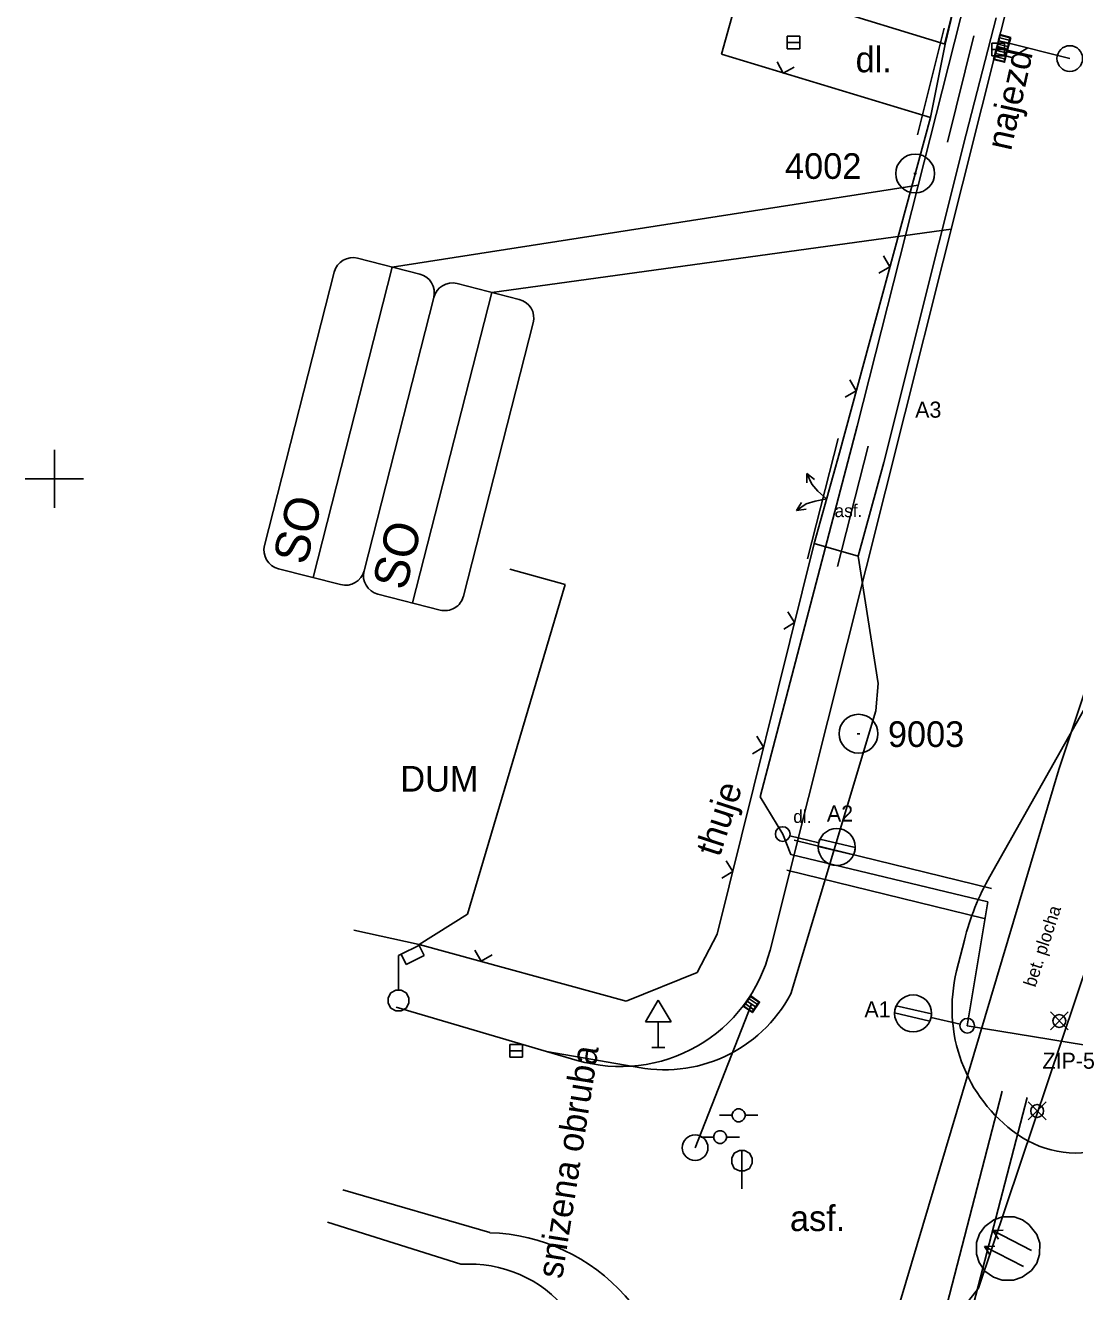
# Model space of a CAD drawing. Extents: x -733601 to -733291, y -1137892 to -1137187.
# Drawn here: x -733501.13 to -733460.25, y -1137631.66 to -1137582.33 of the extents above; entities that cross this region are included whole.
import ezdxf

# ---------------------------------------------------------------- set-up
doc = ezdxf.new("R2010")
doc.units = 0
for name, color, linetype in [('BP_NOVE_NAVRH', 7, 'Continuous'), ('BP_PBPP_pouzito_pro_map_podklady', 7, 'Continuous'), ('Default', 7, 'Continuous'), ('Krizky_Hektom_sit', 7, 'Continuous'), ('SIT_PROJ', 7, 'Continuous'), ('SIT_PUV_BUS', 7, 'Continuous')]:
    doc.layers.add(name, color=color, linetype=linetype)

# ---------------------------------------------------------------- blocks, each defined once
blk = doc.blocks.new('T_PS_1_1_2')
at = {"layer": 'Default'}
blk.add_line((-12.486, 3.717), (12.486, 3.717), dxfattribs=at)
for points in [[(10.986, 8), (-10.986, 8)], [(-12.486, 6.5), (-12.486, 1.5)], [(12.486, 1.5), (12.486, 6.5)], [(-10.986, 0), (10.986, 0)]]:
    blk.add_lwpolyline(points, dxfattribs=at)
for centre, start, end in [((-10.986, 6.5), 90, 180), ((10.986, 6.5), 0, 90), ((-10.986, 1.5), 180, 270), ((10.986, 1.5), 270, 360)]:
    blk.add_arc(centre, 1.5, start, end, dxfattribs=at)
blk.add_text('SO', height=2.7, dxfattribs=at).set_placement((-11.75, 4.466))
blk = doc.blocks.new('DOPRAVA_4$0$SYMB1230')
at = {"layer": 'Default'}
for p, q in [((-0.1, -0.329897), (-0.1, -0.020619)), ((-0.1, -0.325773), (-0.1, -0.329897)), ((0, -0.020619), (0, -0.329897)), ((0.1, -0.020619), (0.1, -0.329897))]:
    blk.add_line(p, q, dxfattribs=at)
for points in [[(-0.2, 0), (0.2, 0), (0.2, -0.35), (-0.2, -0.35)], [(-0.182831, -0.020619), (0.181696, -0.020619), (0.181696, -0.329897), (-0.182831, -0.329897)]]:
    blk.add_lwpolyline(points, close=True, dxfattribs=at)
blk = doc.blocks.new('T_PS_1_2')
at = {"layer": 'Default'}
blk.add_line((-12.486, 3.717), (12.486, 3.717), dxfattribs=at)
for points in [[(10.986, 8), (-10.986, 8)], [(-12.486, 6.5), (-12.486, 1.5)], [(12.486, 1.5), (12.486, 6.5)], [(-10.986, 0), (10.986, 0)]]:
    blk.add_lwpolyline(points, dxfattribs=at)
for centre, start, end in [((-10.986, 6.5), 90, 180), ((10.986, 6.5), 0, 90), ((-10.986, 1.5), 180, 270), ((10.986, 1.5), 270, 360)]:
    blk.add_arc(centre, 1.5, start, end, dxfattribs=at)
blk.add_text('SO', height=2.7, dxfattribs=at).set_placement((-11.75, 4.466))
blk = doc.blocks.new('POINT_DISPLAY')
at = {"layer": 'Default'}
for p, q in [((-0.7, -0.7), (0.7, 0.7)), ((-0.7, 0.7), (0.7, -0.7))]:
    blk.add_line(p, q, dxfattribs=at)
blk.add_circle((0, 0), 0.5, dxfattribs=at)
blk = doc.blocks.new('vytyc_bod_MP')
at = {"layer": 'Default'}
blk.add_blockref('POINT_DISPLAY', (0, 0), dxfattribs=at)

msp = doc.modelspace()

# ---------------------------------------------------------------- linework, layer by layer
at = {"layer": 'BP_NOVE_NAVRH'}
msp.add_line((-733466.512, -1137588.104), (-733466.412, -1137588.104), dxfattribs=at)
msp.add_circle((-733466.462, -1137588.104), 0.756, dxfattribs=at)
at = {"layer": 'BP_PBPP_pouzito_pro_map_podklady'}
msp.add_line((-733468.718, -1137609.925), (-733468.618, -1137609.925), dxfattribs=at)
msp.add_circle((-733468.668, -1137609.925), 0.756, dxfattribs=at)
at = {"layer": 'Krizky_Hektom_sit'}
for p, q in [((-733500, -1137601.131), (-733500, -1137598.869)), ((-733498.869, -1137600), (-733501.131, -1137600))]:
    msp.add_line(p, q, dxfattribs=at)
at = {"layer": 'SIT_PROJ'}
for p, q in [((-733470.218, -1137614.172), (-733471.343, -1137613.903)), ((-733465.84, -1137620.98), (-733464.711, -1137621.236))]:
    msp.add_line(p, q, dxfattribs=at)
for points in [[(-733472.116, -1137618.354), (-733450.389, -1137531.821), (-733445.369, -1137510.61)], [(-733443.713, -1137537.937), (-733443.53, -1137546.097), (-733458.871, -1137607.201), (-733463.551, -1137615.482)], [(-733467.9, -1137562.59), (-733460.704, -1137564.688), (-733465.317, -1137583.062)], [(-733457.917, -1137622.364), (-733464.433, -1137621.3), (-733463.63, -1137616.478), (-733471.299, -1137614.635), (-733471.621, -1137613.836), (-733472.5, -1137612.391), (-733468.724, -1137597.945), (-733462.8, -1137574.579)], [(-733466.364, -1137586.591), (-733465.335, -1137582.447)], [(-733465.2, -1137586.88), (-733464.17, -1137582.736)], [(-733463.021, -1137582.973), (-733460.431, -1137583.625)], [(-733463.132, -1137583.473), (-733462.692, -1137583.584), (-733462.07, -1137583.212)], [(-733466.343, -1137588.552), (-733486.834, -1137591.746), (-733486.834, -1137591.746)], [(-733465.064, -1137590.27), (-733482.959, -1137592.735), (-733482.959, -1137592.735)], [(-733470.65, -1137603.114), (-733469.457, -1137598.43)], [(-733469.487, -1137603.41), (-733468.294, -1137598.726)], [(-733471.17, -1137614.074), (-733463.486, -1137615.957)], [(-733468.798, -1137614.364), (-733470.17, -1137614.035)], [(-733470.17, -1137614.035), (-733468.798, -1137614.364)], [(-733470.237, -1137614.315), (-733468.865, -1137614.644)], [(-733470.237, -1137614.315), (-733468.865, -1137614.644)], [(-733471.455, -1137615.239), (-733463.771, -1137617.123)], [(-733464.544, -1137617.966), (-733464.845, -1137619.165)], [(-733472.841, -1137620.461), (-733475.03, -1137626.052)], [(-733465.823, -1137620.837), (-733467.198, -1137620.524)], [(-733465.823, -1137620.837), (-733467.198, -1137620.524)], [(-733467.262, -1137620.805), (-733465.886, -1137621.118)], [(-733465.886, -1137621.118), (-733467.262, -1137620.805)], [(-733480.819, -1137622.3), (-733479.625, -1137622.651)], [(-733463.07, -1137623.85), (-733466.099, -1137635.551)], [(-733462.101, -1137624.1), (-733465.131, -1137635.801)]]:
    msp.add_lwpolyline(points, dxfattribs=at)
for centre, radius in [((-733460.435, -1137583.625), 0.5), ((-733471.621, -1137613.836), 0.286), ((-733471.621, -1137613.836), 0.286), ((-733469.517, -1137614.34), 0.72), ((-733466.542, -1137620.821), 0.72), ((-733464.433, -1137621.3), 0.286), ((-733464.433, -1137621.3), 0.286), ((-733475.034, -1137626.052), 0.5)]:
    msp.add_circle(centre, radius, dxfattribs=at)
for centre, radius, start, end in [((-733469.517, -1137614.34), 0.72, 154.9831, 178.0588), ((-733469.517, -1137614.34), 0.72, 334.9831, 358.0588), ((-733454.845, -1137620.402), 10, 150.5296, 165.9059), ((-733477.935, -1137616.893), 6, 253.6422, 345.9059), ((-733459.025, -1137620.626), 6, 165.9059, 234.8056), ((-733466.542, -1137620.821), 0.72, 155.6562, 178.7319), ((-733466.542, -1137620.821), 0.72, 335.6562, 358.7319), ((-733460.178, -1137622.261), 4, 234.8056, 345.9059), ((-733459.33, -1137625.042), 10, 255.9059, 345.9059)]:
    msp.add_arc(centre, radius, start, end, dxfattribs=at)
at = {"layer": 'SIT_PUV_BUS'}
for p, q in [((-733465.29, -1137583.07), (-733460.94, -1137564.62)), ((-733472.88, -1137579.44), (-733474.01, -1137583.46)), ((-733465.29, -1137583.07), (-733470.22, -1137581.56)), ((-733463.31, -1137582.04), (-733464.48, -1137586.57)), ((-733470.95, -1137582.75), (-733471.45, -1137582.75)), ((-733471.45, -1137582.75), (-733471.45, -1137583.25)), ((-733470.95, -1137583), (-733471.45, -1137583)), ((-733470.95, -1137583.25), (-733470.95, -1137582.75)), ((-733462.98, -1137583.02), (-733463.48, -1137583.02)), ((-733463.48, -1137583.02), (-733463.48, -1137583.52)), ((-733462.98, -1137583.52), (-733462.98, -1137583.02)), ((-733474.01, -1137583.46), (-733465.87, -1137585.92)), ((-733471.45, -1137583.25), (-733470.95, -1137583.25)), ((-733465.87, -1137585.92), (-733465.29, -1137583.07)), ((-733462.98, -1137583.27), (-733463.48, -1137583.27)), ((-733463.48, -1137583.52), (-733462.98, -1137583.52)), ((-733471.844, -1137583.754), (-733471.61, -1137584.19)), ((-733471.61, -1137584.19), (-733471.174, -1137583.956)), ((-733469.41, -1137598.98), (-733465.87, -1137585.92)), ((-733464.48, -1137586.57), (-733467.68, -1137599.36)), ((-733453.82, -1137590.07), (-733460.86, -1137611.32)), ((-733467.45, -1137591.74), (-733467.696, -1137591.31)), ((-733467.88, -1137591.986), (-733467.45, -1137591.74)), ((-733468.76, -1137596.57), (-733469.006, -1137596.14)), ((-733469.19, -1137596.816), (-733468.76, -1137596.57)), ((-733470.4, -1137602.52), (-733469.41, -1137598.98)), ((-733470.487, -1137600.207), (-733470.682, -1137599.789)), ((-733470.682, -1137599.789), (-733470.679, -1137600.153)), ((-733470.682, -1137599.789), (-733470.385, -1137600.027)), ((-733467.68, -1137599.36), (-733468.68, -1137603.01)), ((-733470.252, -1137600.48), (-733470.487, -1137600.207)), ((-733470.359, -1137600.865), (-733469.92, -1137600.78)), ((-733469.92, -1137600.78), (-733470.252, -1137600.48)), ((-733471.085, -1137601.234), (-733470.894, -1137600.923)), ((-733471.085, -1137601.234), (-733470.702, -1137600.977)), ((-733471.085, -1137601.234), (-733470.707, -1137601.183)), ((-733470.702, -1137600.977), (-733470.359, -1137600.865)), ((-733474.17, -1137617.73), (-733470.4, -1137602.52)), ((-733470.4, -1137602.52), (-733468.68, -1137603.01)), ((-733468.68, -1137603.01), (-733467.9, -1137607.97)), ((-733480.1, -1137604.11), (-733482.26, -1137603.51)), ((-733483.9, -1137616.96), (-733480.1, -1137604.11)), ((-733471.16, -1137605.6), (-733471.416, -1137605.176)), ((-733471.584, -1137605.856), (-733471.16, -1137605.6)), ((-733467.9, -1137607.97), (-733467.99, -1137609.04)), ((-733467.99, -1137609.04), (-733471.31, -1137620.06)), ((-733472.37, -1137610.45), (-733472.626, -1137610.026)), ((-733472.794, -1137610.706), (-733472.37, -1137610.45)), ((-733460.86, -1137611.32), (-733468.24, -1137636.02)), ((-733457.34, -1137611.69), (-733463.99, -1137631.53)), ((-733473.57, -1137615.3), (-733473.826, -1137614.876)), ((-733473.994, -1137615.556), (-733473.57, -1137615.3)), ((-733483.9, -1137616.96), (-733485.79, -1137618.14)), ((-733485.79, -1137618.14), (-733488.33, -1137617.58)), ((-733474.95, -1137619.23), (-733474.17, -1137617.73)), ((-733486.59, -1137618.57), (-733485.69, -1137618.12)), ((-733486.29, -1137618.92), (-733486.49, -1137618.52)), ((-733485.79, -1137618.14), (-733477.72, -1137620.34)), ((-733485.79, -1137618.17), (-733485.59, -1137618.57)), ((-733483.616, -1137618.36), (-733483.37, -1137618.79)), ((-733483.37, -1137618.79), (-733482.94, -1137618.544)), ((-733486.59, -1137619.92), (-733486.59, -1137618.57)), ((-733485.59, -1137618.57), (-733486.29, -1137618.92)), ((-733477.72, -1137620.34), (-733474.95, -1137619.23)), ((-733486.99, -1137620.22), (-733486.89, -1137620.02)), ((-733486.89, -1137620.02), (-733486.69, -1137619.92)), ((-733486.69, -1137619.92), (-733486.49, -1137619.92)), ((-733486.49, -1137619.92), (-733486.29, -1137620.02)), ((-733486.29, -1137620.02), (-733486.19, -1137620.22)), ((-733486.99, -1137620.42), (-733486.99, -1137620.22)), ((-733486.89, -1137620.62), (-733486.99, -1137620.42)), ((-733486.19, -1137620.42), (-733486.29, -1137620.62)), ((-733486.19, -1137620.22), (-733486.19, -1137620.42)), ((-733476.47, -1137620.3), (-733476.97, -1137621.15)), ((-733475.97, -1137621.15), (-733476.47, -1137620.3)), ((-733486.69, -1137620.72), (-733486.89, -1137620.62)), ((-733486.49, -1137620.72), (-733486.69, -1137620.72)), ((-733480.82, -1137622.3), (-733486.68, -1137620.58)), ((-733486.29, -1137620.62), (-733486.49, -1137620.72)), ((-733476.97, -1137621.15), (-733475.97, -1137621.15)), ((-733476.47, -1137622.15), (-733476.47, -1137621.15)), ((-733481.76, -1137622.03), (-733482.26, -1137622.03)), ((-733482.26, -1137622.03), (-733482.26, -1137622.53)), ((-733481.76, -1137622.28), (-733482.26, -1137622.28)), ((-733481.76, -1137622.53), (-733481.76, -1137622.03)), ((-733477.45, -1137622.89), (-733480.82, -1137622.3)), ((-733476.72, -1137622.15), (-733476.22, -1137622.15)), ((-733482.26, -1137622.53), (-733481.76, -1137622.53)), ((-733474.09, -1137624.79), (-733473.59, -1137624.79)), ((-733473.59, -1137624.74), (-733473.54, -1137624.64)), ((-733473.59, -1137624.84), (-733473.59, -1137624.74)), ((-733473.54, -1137624.94), (-733473.59, -1137624.84)), ((-733473.54, -1137624.64), (-733473.49, -1137624.59)), ((-733473.49, -1137624.99), (-733473.54, -1137624.94)), ((-733473.49, -1137624.59), (-733473.39, -1137624.54)), ((-733473.39, -1137624.54), (-733473.29, -1137624.54)), ((-733473.29, -1137624.54), (-733473.19, -1137624.59)), ((-733473.19, -1137624.59), (-733473.14, -1137624.64)), ((-733473.14, -1137624.94), (-733473.19, -1137624.99)), ((-733473.14, -1137624.64), (-733473.09, -1137624.74)), ((-733473.09, -1137624.84), (-733473.14, -1137624.94)), ((-733473.09, -1137624.74), (-733473.09, -1137624.84)), ((-733473.09, -1137624.79), (-733472.59, -1137624.79)), ((-733474.26, -1137625.49), (-733474.21, -1137625.44)), ((-733474.21, -1137625.44), (-733474.11, -1137625.39)), ((-733474.11, -1137625.39), (-733474.01, -1137625.39)), ((-733474.01, -1137625.39), (-733473.91, -1137625.44)), ((-733473.91, -1137625.44), (-733473.86, -1137625.49)), ((-733473.39, -1137625.04), (-733473.49, -1137624.99)), ((-733473.29, -1137625.04), (-733473.39, -1137625.04)), ((-733473.19, -1137624.99), (-733473.29, -1137625.04)), ((-733474.81, -1137625.64), (-733474.31, -1137625.64)), ((-733474.31, -1137625.59), (-733474.26, -1137625.49)), ((-733474.31, -1137625.69), (-733474.31, -1137625.59)), ((-733474.26, -1137625.79), (-733474.31, -1137625.69)), ((-733474.21, -1137625.84), (-733474.26, -1137625.79)), ((-733474.11, -1137625.89), (-733474.21, -1137625.84)), ((-733474.01, -1137625.89), (-733474.11, -1137625.89)), ((-733473.91, -1137625.84), (-733474.01, -1137625.89)), ((-733473.86, -1137625.79), (-733473.91, -1137625.84)), ((-733473.86, -1137625.49), (-733473.81, -1137625.59)), ((-733473.81, -1137625.69), (-733473.86, -1137625.79)), ((-733473.81, -1137625.59), (-733473.81, -1137625.69)), ((-733473.81, -1137625.64), (-733473.31, -1137625.64)), ((-733473.61, -1137626.46), (-733473.51, -1137626.26)), ((-733473.51, -1137626.26), (-733473.31, -1137626.16)), ((-733473.31, -1137626.16), (-733473.11, -1137626.16)), ((-733473.21, -1137626.16), (-733473.21, -1137627.66)), ((-733473.11, -1137626.16), (-733472.91, -1137626.26)), ((-733472.91, -1137626.26), (-733472.81, -1137626.46)), ((-733473.61, -1137626.66), (-733473.61, -1137626.46)), ((-733473.51, -1137626.86), (-733473.61, -1137626.66)), ((-733473.31, -1137626.96), (-733473.51, -1137626.86)), ((-733472.91, -1137626.86), (-733473.11, -1137626.96)), ((-733472.81, -1137626.66), (-733472.91, -1137626.86)), ((-733472.81, -1137626.46), (-733472.81, -1137626.66)), ((-733473.11, -1137626.96), (-733473.31, -1137626.96)), ((-733488.76, -1137627.69), (-733483.03, -1137629.36)), ((-733463.75, -1137629.123), (-733463.391, -1137628.858)), ((-733463.391, -1137628.858), (-733463.054, -1137628.749)), ((-733463.054, -1137628.749), (-733462.607, -1137628.752)), ((-733462.607, -1137628.752), (-733462.273, -1137628.866)), ((-733462.273, -1137628.866), (-733462.028, -1137629.047)), ((-733489.36, -1137628.95), (-733484.16, -1137630.59)), ((-733463.954, -1137629.413), (-733463.75, -1137629.123)), ((-733463.438, -1137629.282), (-733463.036, -1137629.263)), ((-733461.924, -1137630.054), (-733463.438, -1137629.282)), ((-733463.438, -1137629.282), (-733463.217, -1137629.619)), ((-733462.028, -1137629.047), (-733461.718, -1137629.429)), ((-733464.071, -1137630.194), (-733464.068, -1137629.747)), ((-733464.068, -1137629.747), (-733463.954, -1137629.413)), ((-733463.756, -1137629.906), (-733463.354, -1137629.887)), ((-733461.718, -1137629.429), (-733461.609, -1137629.766)), ((-733461.609, -1137629.766), (-733461.612, -1137630.213)), ((-733463.962, -1137630.531), (-733464.071, -1137630.194)), ((-733463.756, -1137629.906), (-733462.242, -1137630.678)), ((-733463.756, -1137629.906), (-733463.535, -1137630.243)), ((-733461.612, -1137630.213), (-733461.726, -1137630.547)), ((-733463.741, -1137630.868), (-733463.962, -1137630.531)), ((-733463.407, -1137631.094), (-733463.741, -1137630.868)), ((-733461.93, -1137630.837), (-733462.289, -1137631.102)), ((-733461.726, -1137630.547), (-733461.93, -1137630.837)), ((-733463.073, -1137631.208), (-733463.407, -1137631.094)), ((-733462.626, -1137631.211), (-733463.073, -1137631.208)), ((-733462.289, -1137631.102), (-733462.626, -1137631.211)), ((-733463.99, -1137631.53), (-733464.8, -1137632.55))]:
    msp.add_line(p, q, dxfattribs=at)
for centre, radius, start, end in [((-733476.23, -1137617.44), 5.578, 257.3904, 331.955), ((-733483.25, -1137636.73), 7.367, 355.261, 88.2848), ((-733483.82, -1137635.47), 4.886, 343.7447, 93.9812)]:
    msp.add_arc(centre, radius, start, end, dxfattribs=at)

# ---------------------------------------------------------------- block references
at = {"layer": 'SIT_PROJ'}
for name, p, xscale, yscale, rotation in [('DOPRAVA_4$0$SYMB1230', (-733462.799, -1137583.042), 1.2499999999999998, 1.2499999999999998, -104.0941086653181), ('DOPRAVA_4$0$SYMB1230', (-733462.92, -1137583.526), 1.2499999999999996, 1.2499999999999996, -103.90977566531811), ('T_PS_1_2', (-733486.577, -1137598.255), 0.49999999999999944, 0.49999999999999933, 75.68569569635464), ('T_PS_1_1_2', (-733482.701, -1137599.244), 0.4999999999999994, 0.4999999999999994, 75.68569569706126), ('DOPRAVA_4$0$SYMB1230', (-733473.022, -1137620.336), 1.25, 1.25, 55.337166)]:
    msp.add_blockref(name, p, dxfattribs=dict(at, xscale=xscale, yscale=yscale, rotation=rotation))
at = {"layer": 'SIT_PROJ', "xscale": 0.5, "yscale": 0.5}
for p in [(-733460.844, -1137621.116), (-733461.708, -1137624.62)]:
    msp.add_blockref('vytyc_bod_MP', p, dxfattribs=at)

# ---------------------------------------------------------------- texts
at = {"layer": 'BP_NOVE_NAVRH'}
msp.add_text('4002', height=1, dxfattribs=at).set_placement((-733471.532, -1137588.313))
at = {"layer": 'BP_PBPP_pouzito_pro_map_podklady'}
msp.add_text('9003', height=1, dxfattribs=at).set_placement((-733467.523, -1137610.443))
at = {"layer": 'SIT_PROJ'}
for s, p in [('A3', (-733466.462, -1137597.615)), ('A2', (-733469.9, -1137613.347)), ('A1', (-733468.439, -1137620.974)), ('ZIP-5', (-733461.503, -1137622.977))]:
    msp.add_text(s, height=0.625, rotation=360, dxfattribs=at).set_placement(p)
at = {"layer": 'SIT_PUV_BUS'}
for s, height, p in [('dl.', 1, (-733468.78, -1137584.16)), ('asf.', 0.5, (-733469.6, -1137601.49)), ('DUM', 1, (-733486.52, -1137612.18)), ('dl.', 0.5, (-733471.21, -1137613.4)), ('asf.', 1, (-733471.34, -1137629.3))]:
    msp.add_text(s, height=height, dxfattribs=at).set_placement(p)
for s, height, rotation, p in [('najezd', 1, 77.4, (-733462.73, -1137587.25)), ('thuje', 1, 72, (-733474.08, -1137614.76)), ('bet. plocha', 0.5, 72, (-733461.78, -1137619.83)), ('snizena obruba', 1, 81, (-733480.22, -1137631.19))]:
    msp.add_text(s, height=height, rotation=rotation, dxfattribs=at).set_placement(p)

doc.saveas('drawing.dxf')
